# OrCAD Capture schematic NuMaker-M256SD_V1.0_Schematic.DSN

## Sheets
1 Nu-Link2-Me: size A3; title: Nu-Link2-Me; rev: 1.0; company: CMHuang; note: Nu-Link2-Me
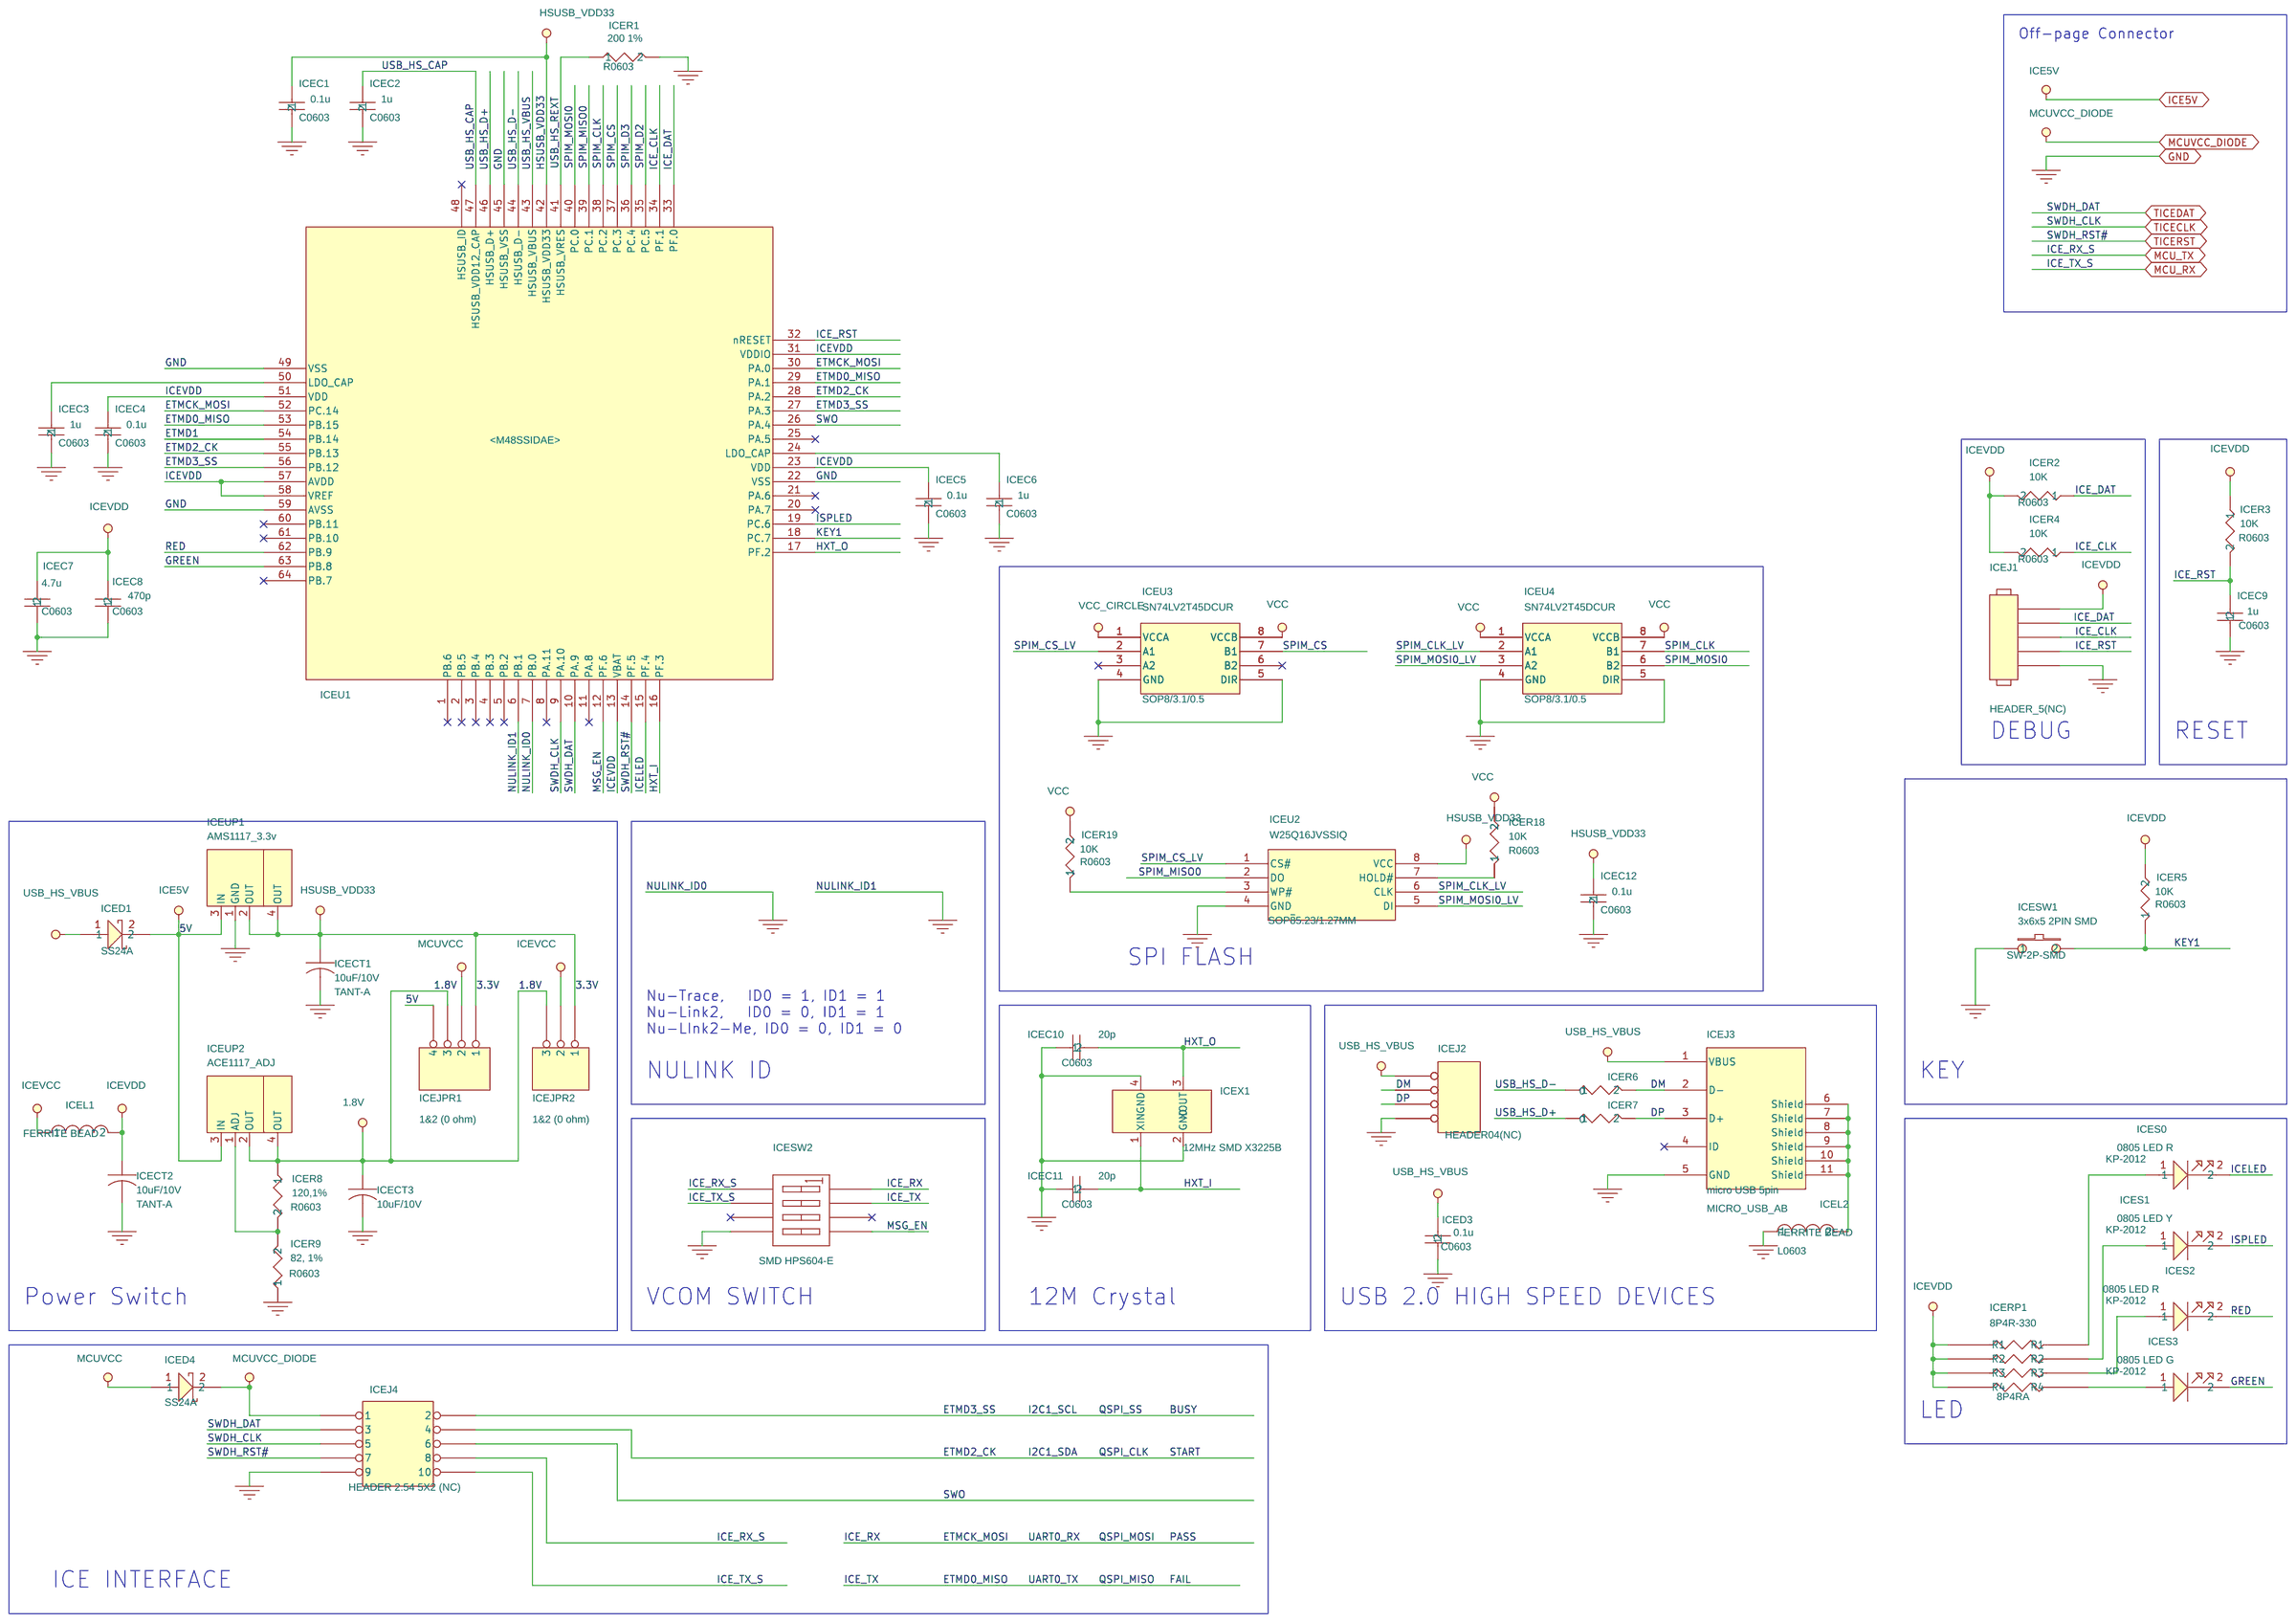
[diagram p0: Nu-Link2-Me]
2 M256SD2AE: size Custom; title: M256SD2AE; rev: v1.0; note: NuMaker-PFM-M256SD
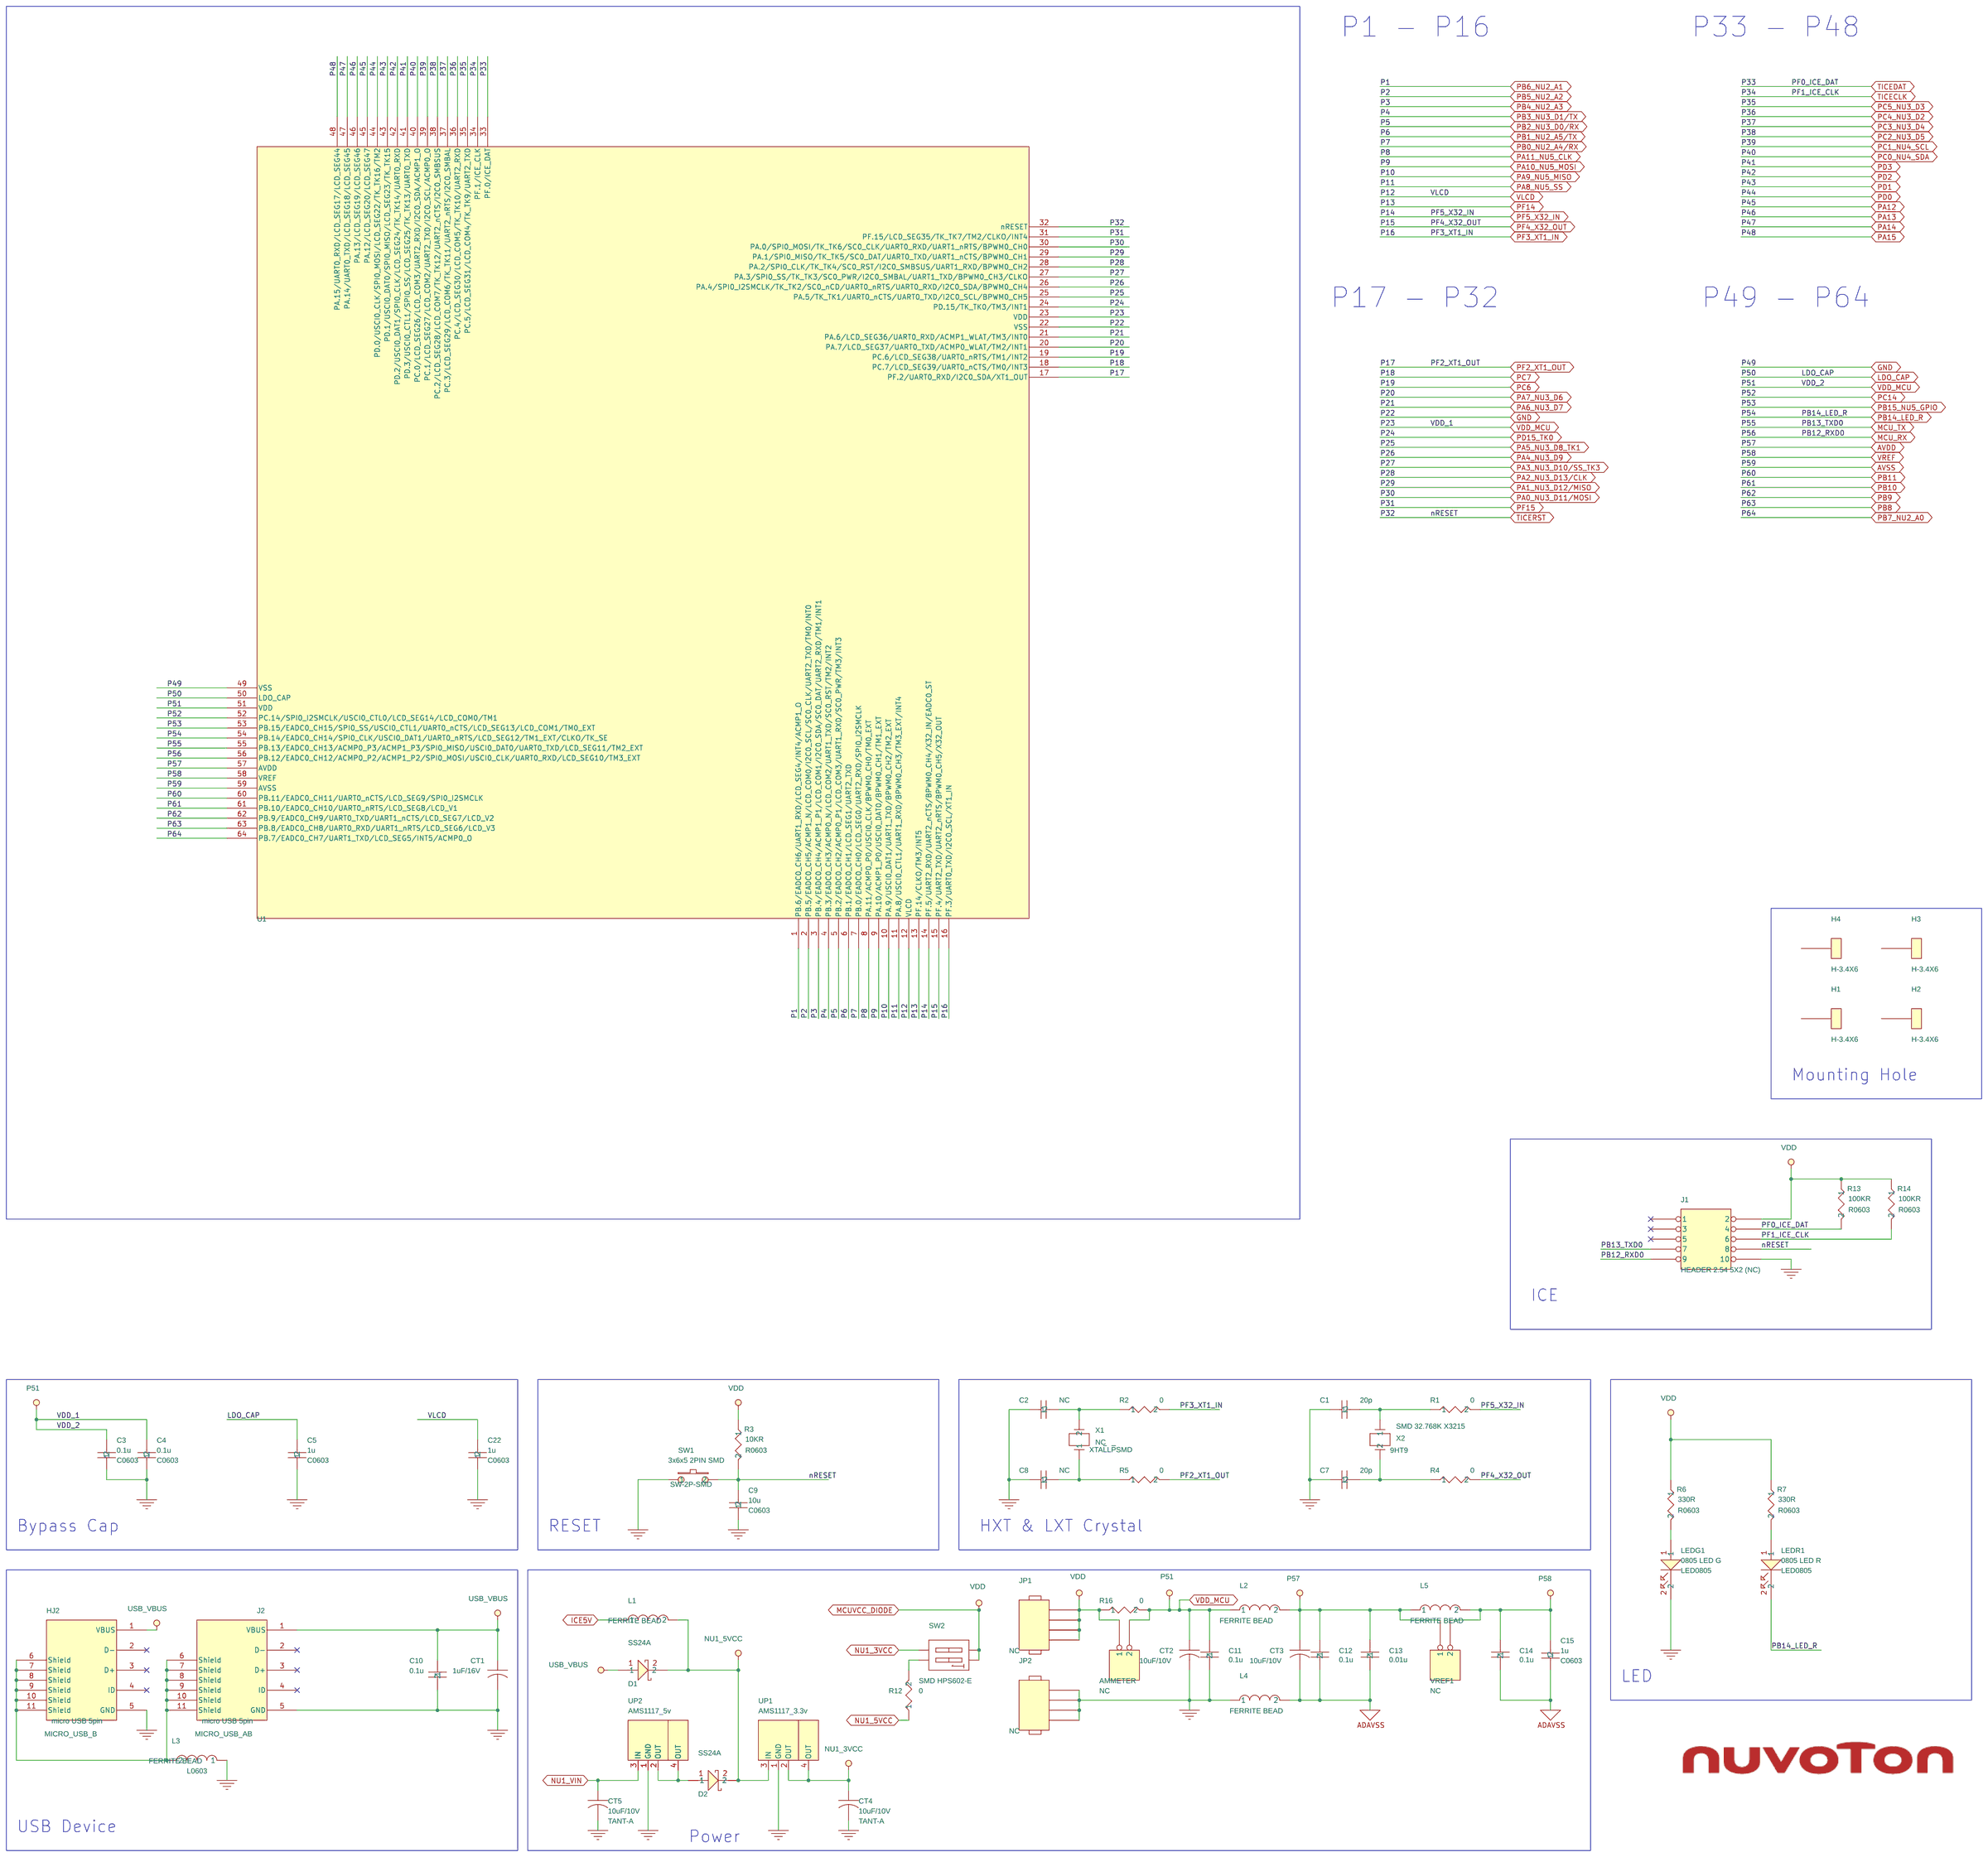
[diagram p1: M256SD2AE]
3 Ext. Connector: size Custom; title: Ext. Connector; rev: v1.0; note: NuMaker-PFM-M256SD
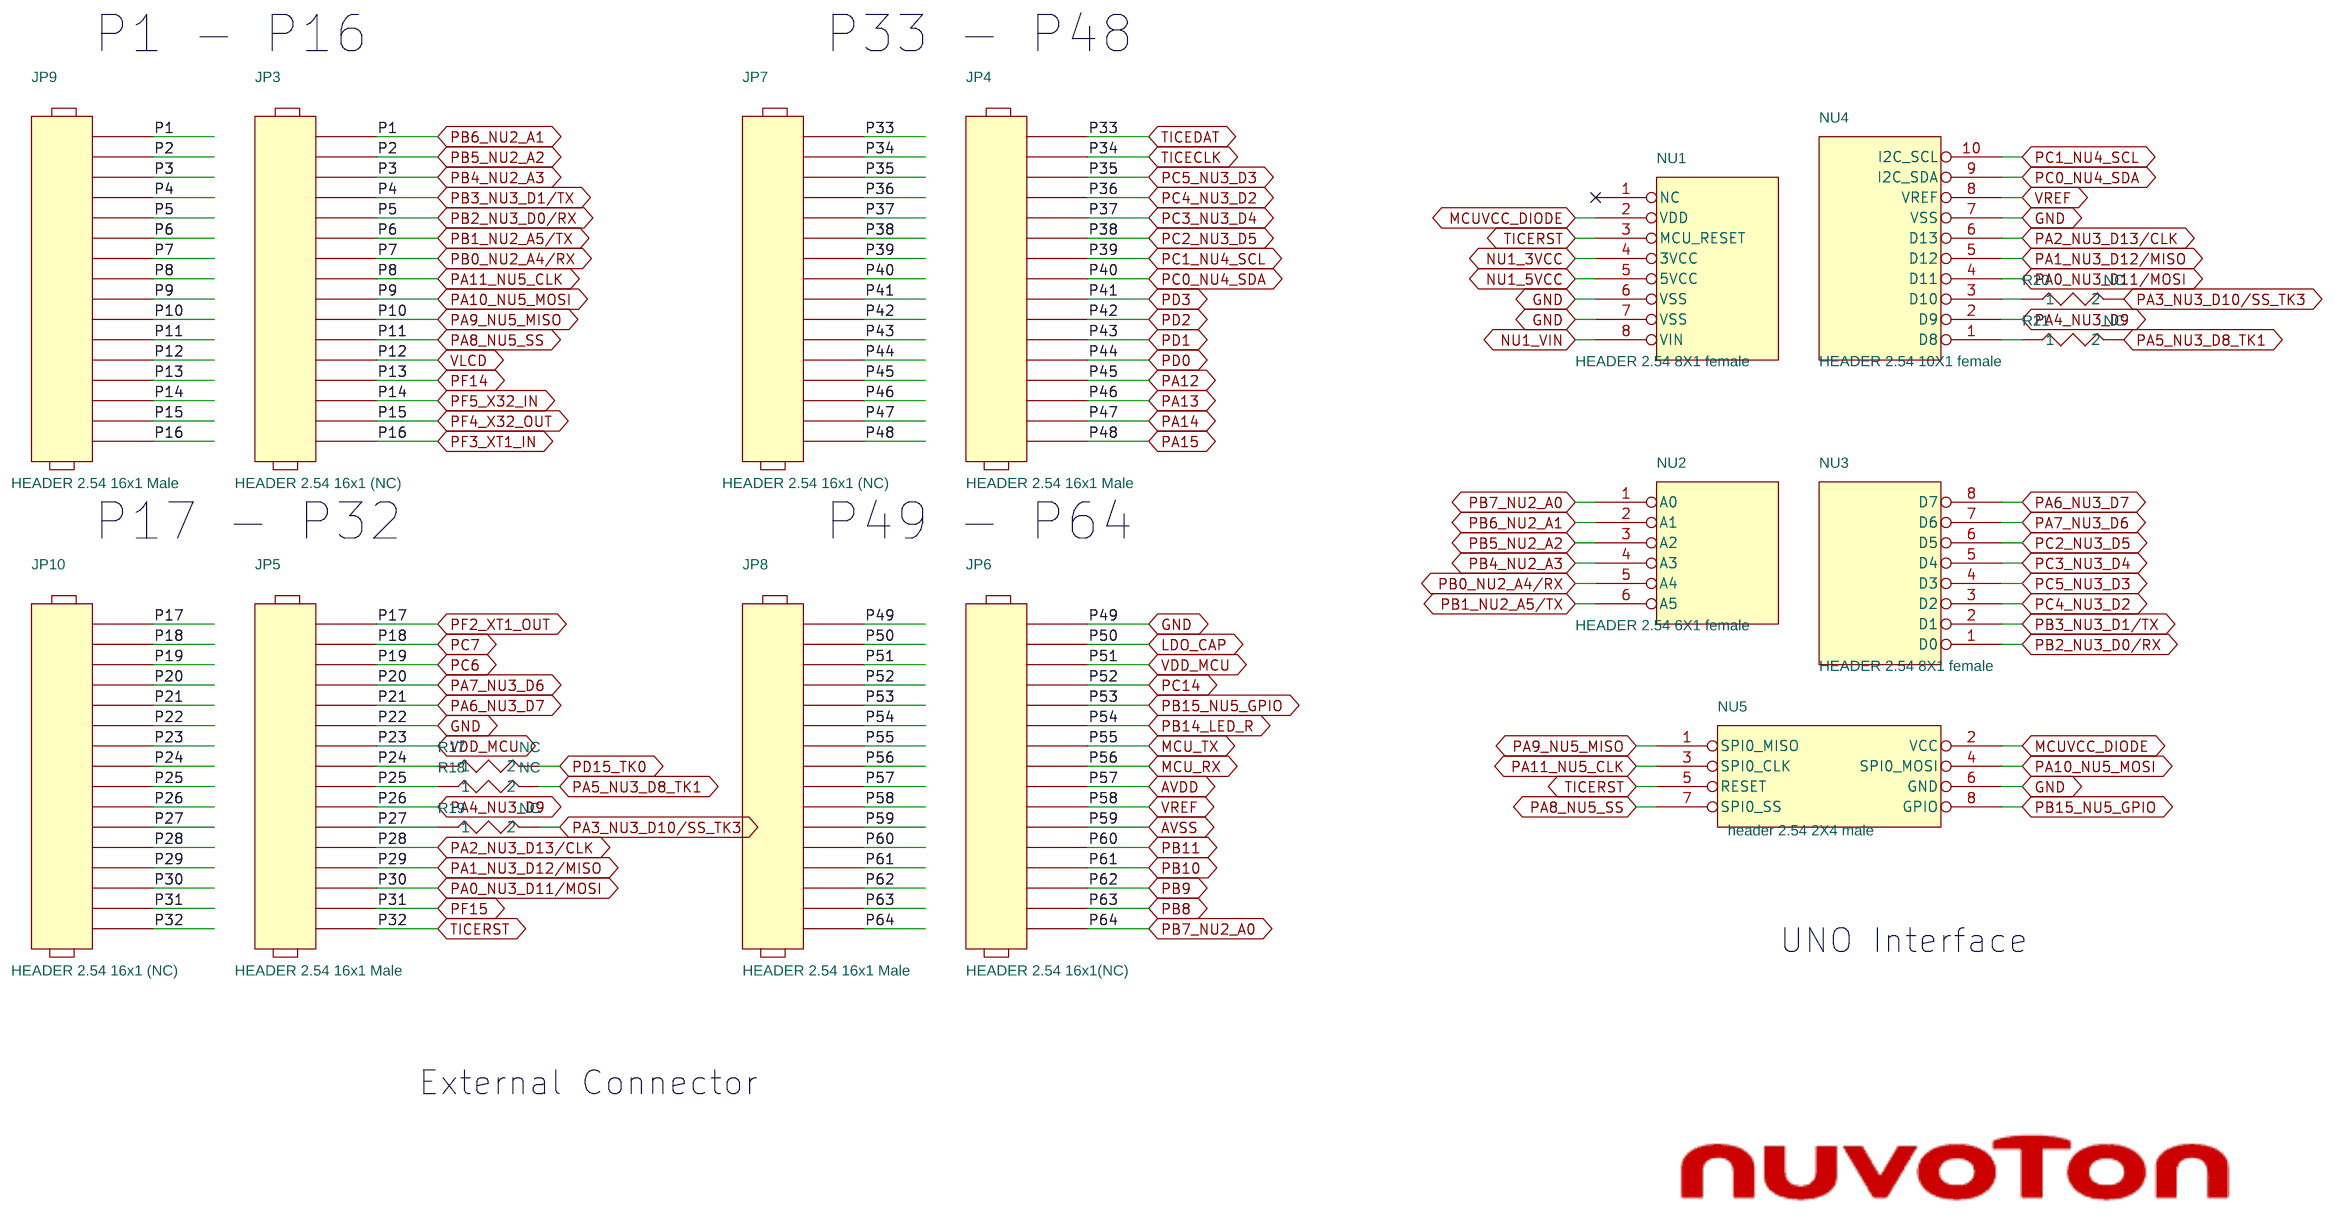
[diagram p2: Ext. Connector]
4 Touch Key: size A; title: Touch Key; rev: v1.0; note: NuMaker-PFM-M256SD
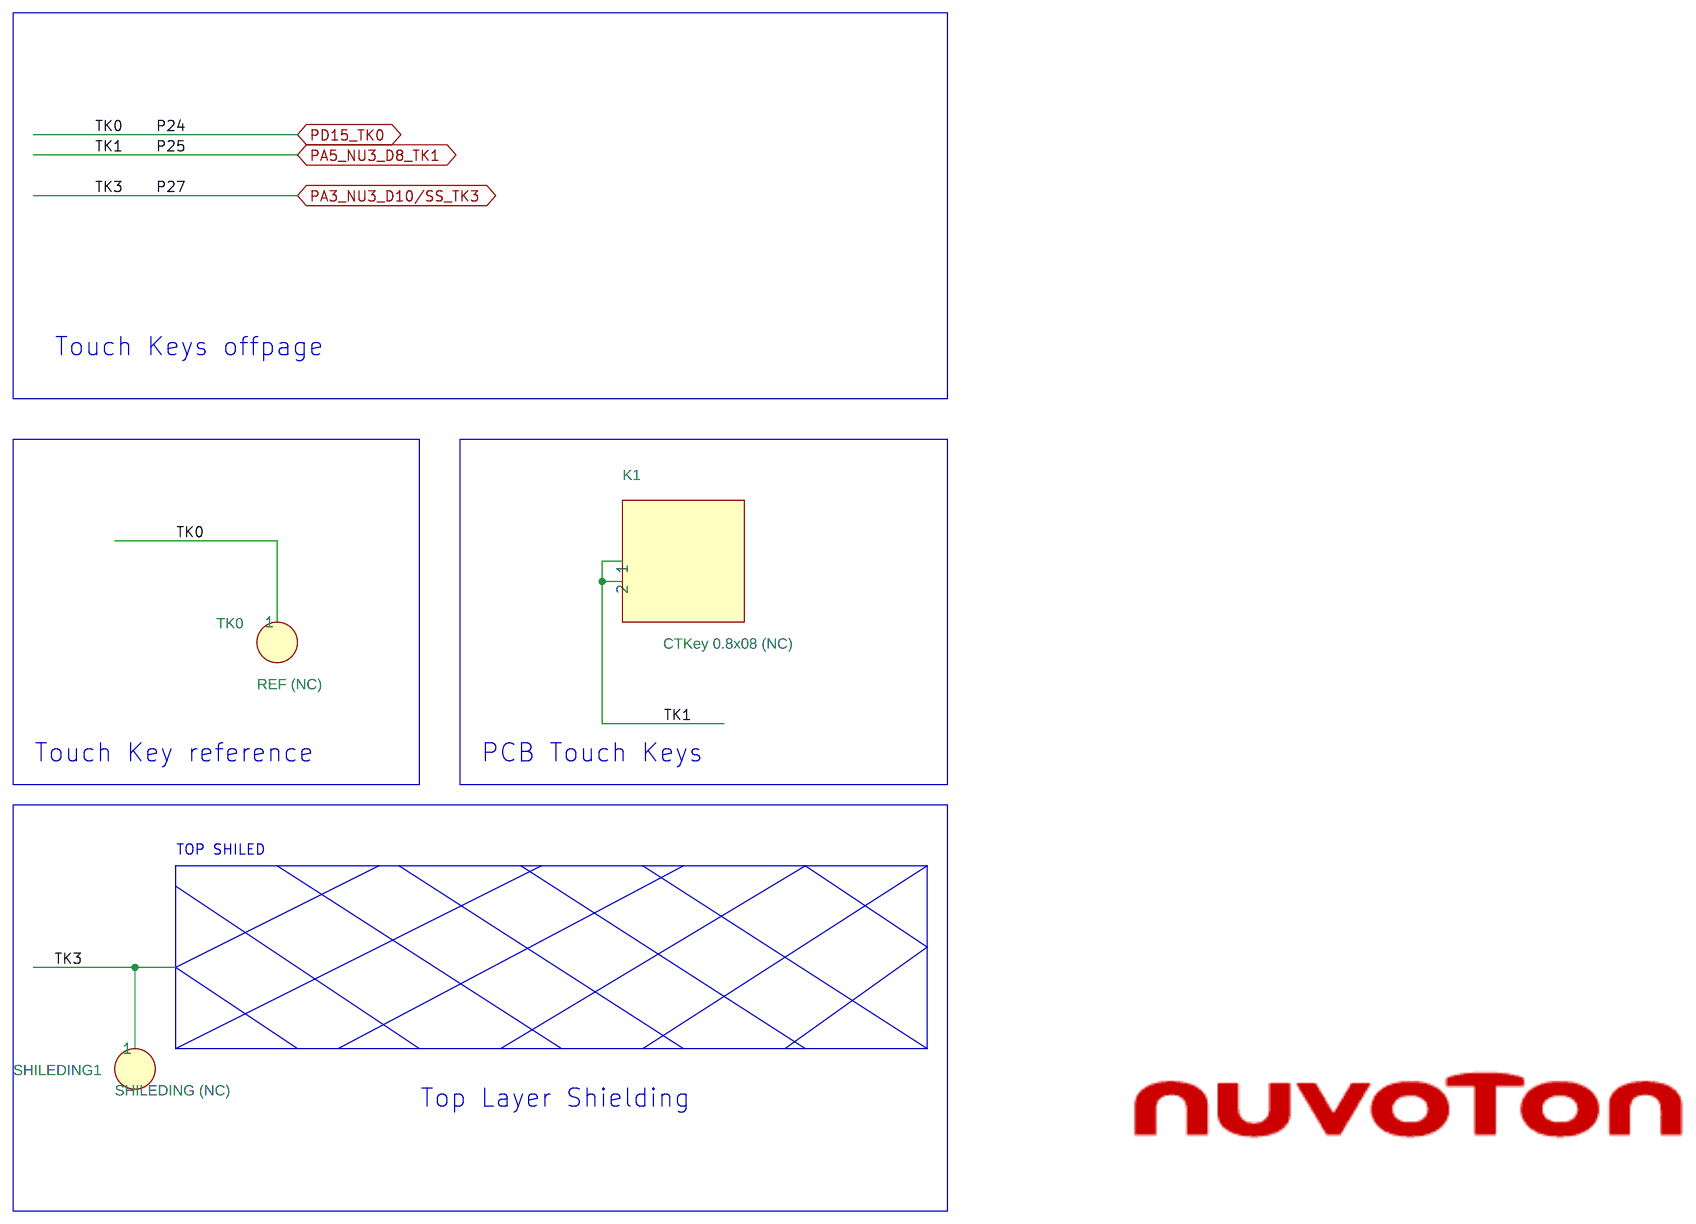
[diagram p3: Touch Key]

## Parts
sheet Ext. Connector
JP3  HEADER 2.54 16x1 (NC)  [HEADER16X1]
JP4  HEADER 2.54 16x1 Male  [HEADER16X1]
JP5  HEADER 2.54 16x1 Male  [HEADER16X1]
JP6  HEADER 2.54 16x1(NC)  [HEADER16X1]
JP7  HEADER 2.54 16x1 (NC)  [HEADER16X1]
JP8  HEADER 2.54 16x1 Male  [HEADER16X1]
JP9  HEADER 2.54 16x1 Male  [HEADER16X1]
JP10  HEADER 2.54 16x1 (NC)  [HEADER16X1]
NU1  HEADER 2.54 8X1 female  [SIP-8P]
NU2  HEADER 2.54 6X1 female  [SIP-6P]
NU3  HEADER 2.54 8X1 female  [SIP-8P]
NU4  HEADER 2.54 10X1 female  [SIP-10P]
NU5  header 2.54 2X4 male  [HEADER4X2]
R17  NC  [R0603]
R18  NC  [R0603]
R19  NC  [R0603]
R20  NC  [R0603]
R21  NC  [R0603]
sheet M256SD2AE
AMMETER  NC  [HEADER2X1]
C1  20p  [C0603]
C2  NC  [C0603]
C3  0.1u  [C0603]
C4  0.1u  [C0603]
C5  1u  [C0603]
C7  20p  [C0603]
C8  NC  [C0603]
C9  10u  [C0603]
C10  0.1u  [C0603]
C11  0.1u  [C0603]
C12  0.1u  [C0603]
C13  0.01u  [C0603]
C14  0.1u  [C0603]
C15  1u  [C0603]
C22  1u  [C0603]
CT1  1uF/16V  [TANT-A]
CT2  10uF/10V  [TANT-A]
CT3  10uF/10V  [TANT-A]
CT4  10uF/10V  [TANT-A]
CT5  10uF/10V  [TANT-A]
D1  SS24A  [RB060L]
D2  SS24A  [RB060L]
H1  H-3.4X6  [H-3.4X6]
H2  H-3.4X6  [H-3.4X6]
H3  H-3.4X6  [H-3.4X6]
H4  H-3.4X6  [H-3.4X6]
HJ2  micro USB 5pin  [MICRO_USB_B]
J1  HEADER 2.54 5X2 (NC)  [HEADER5X2]
J2  micro USB 5pin  [MICRO_USB_AB]
JP1  NC  [header1x4]
JP2  NC  [header1x4]
L1  FERRITE BEAD  [L0603]
L2  FERRITE BEAD  [L0603]
L3  FERRITE BEAD  [L0603]
L4  FERRITE BEAD  [L0603]
L5  FERRITE BEAD  [L0603]
LEDG1  0805 LED G  [LED0805]
LEDR1  0805 LED R  [LED0805]
R1  0  [R0603]
R2  0  [R0603]
R3  10KR  [R0603]
R4  0  [R0603]
R5  0  [R0603]
R6  330R  [R0603]
R7  330R  [R0603]
R12  0  [R0603]
R13  100KR  [R0603]
R14  100KR  [R0603]
R16  0  [R0603]
SW1  3x6x5 2PIN SMD  [SW-2P-SMD]
SW2  SMD HPS602-E  [SW1X2]
U1  M256SD2AE  [MCU_LQFP64_7X7mm]
UP1  AMS1117_3.3v  [SOT-223-1]
UP2  AMS1117_5v  [SOT-223-1]
VREF1  NC  [HEADER2X1]
X1  NC  [XTAL\LP\SMD]
X2  SMD 32.768K X3215  [9HT9]
sheet Nu-Link2-Me
ICEC1  0.1u  [C0603]
ICEC2  1u  [C0603]
ICEC3  1u  [C0603]
ICEC4  0.1u  [C0603]
ICEC5  0.1u  [C0603]
ICEC6  1u  [C0603]
ICEC7  4.7u  [C0603]
ICEC8  470p  [C0603]
ICEC9  1u  [C0603]
ICEC10  20p  [C0603]
ICEC11  20p  [C0603]
ICEC12  0.1u  [C0603]
ICECT1  10uF/10V  [TANT-A]
ICECT2  10uF/10V  [TANT-A]
ICECT3  10uF/10V  [TANT-A]
ICED1  SS24A  [RB060L]
ICED3  0.1u  [C0603]
ICED4  SS24A  [RB060L]
ICEJ1  HEADER_5(NC)  [HEADER5X1]
ICEJ2  HEADER04(NC)  [HEADER04]
ICEJ3  micro USB 5pin  [MICRO_USB_AB]
ICEJ4  HEADER 2.54 5X2 (NC)  [HEADER5X2]
ICEJPR1  1&2 (0 ohm)  [R0603X3]
ICEJPR2  1&2 (0 ohm)  [R0603X2]
ICEL1  FERRITE BEAD  [L0603]
ICEL2  FERRITE BEAD  [L0603]
ICER1  200 1%  [R0603]
ICER2  10K  [R0603]
ICER3  10K  [R0603]
ICER4  10K  [R0603]
ICER5  10K  [R0603]
ICER6  0  [R0603]
ICER7  0  [R0603]
ICER8  120,1%  [R0603]
ICER9  82, 1%  [R0603]
ICER18  10K  [R0603]
ICER19  10K  [R0603]
ICERP1  8P4R-330  [8P4RA]
ICES0  0805 LED R  [KP-2012]
ICES1  0805 LED Y  [KP-2012]
ICES2  0805 LED R  [KP-2012]
ICES3  0805 LED G  [KP-2012]
ICESW1  3x6x5 2PIN SMD  [SW-2P-SMD]
ICESW2  SMD HPS604-E  [SW1X4]
ICEU1  M48SSIDAE  [LQFP64_7x7_M48SSIDAE]
ICEU2  W25Q16JVSSIQ  [SOP8\5.23/1.27MM]
ICEU3  SN74LV2T45DCUR  [SOP8/3.1/0.5]
ICEU4  SN74LV2T45DCUR  [SOP8/3.1/0.5]
ICEUP1  AMS1117_3.3v  [SOT-223-1]
ICEUP2  ACE1117_ADJ  [SOT-223-1]
ICEX1  12MHz SMD X3225B  [CRYSTAL_SMD]
sheet Touch Key
K1  CTKey 0.8x08 (NC)  [PAD_8mm]
SHILEDING1  SHILEDING (NC)  [PAD1mm]
TK0  REF (NC)  [PAD1mm]

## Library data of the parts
JP3-JP10 = HEADER_16
NU1 = POWER_CONNECT_0
NU2 = ADC_CONNECT_1
NU3 = PWM0_CONNECT_0
NU4 = PWM1_CONNECT_1
NU5 = NuEdu_NU7
R16 R17 = R_0_2
R2 R18 = R_0_4
R19 = R_0
R1 R20 = R_0_1
R5 R21 = R_0_3
AMMETER = HEADER_2_1
C1 = C_20p_3
C2 = C_20p
C3 = CAP-C_4: Package: 0603; element_no: C0004
C4 ICEC5 = CAP-C: Package: 0603; element_no: C0004
C5 = CAP-C_2: Package: 0603; element_no: C0006
C7 = C_20p_1
C8 = C_20p_2
C9 = CAP-C_5: Package: 0603; element_no: C0006
C10 = C_0.1u_3: element_no: C0004
C11 = C_0.1u: element_no: C0004
C12 = C_0.1u_2: element_no: C0004
C13 = C_0.1u_4: element_no: C0003
C14 = C_0.1u_1: element_no: C0004
C15 ICEC3 = CAP-C_3: Package: 0603; element_no: C0006
C22 = CAP-C_1: Package: 0603; element_no: C0006
CT1 = C_1uF_16V
CT2-CT5 ICECT1-ICECT3 = C_10uF_10V
D1 ICED4 = D_SS24A
D2 ICED1 = D_SS24A_1
H1-H4 = TEST_POINT
HJ2 ICEJ3 J2 = micro_USB_5pin_0
ICEJ4 J1 = HEADER_5X2
JP1 JP2 = HEADER_4
L1 = FERRITE_BEAD_4
L2 = FERRITE_BEAD_2
L3 = FERRITE_BEAD_3
ICEL2 L4 = FERRITE_BEAD_1
ICEL1 L5 = FERRITE_BEAD
LEDG1 = LED_0_1: Package: KP-2012; Vendor: Kingbright
LEDR1 = LED_0: Package: KP-2012; Vendor: Kingbright
ICER1 R3 = R_0_5: Package: 0603
R4 = R_0_10
ICER5 R6 = R_0_8: Package: 0603
ICER8 R7 = R_0: Package: 0603
R12 = R_0_7
ICER18 R13 = R_0_6: Package: 0603
R14 = R_0_9: Package: 0603
ICESW1 SW1 = SW_PUSHBUTTON_0
SW2 = SW_DIP-4_2
U1 = M256SD2AE
ICEUP1 UP1 UP2 = TO-247_Regulator_10
VREF1 = HEADER_2
X1 = Xtal_12MHz
X2 = Xtal_32.768K
ICEC1 = CAP-C_11: Package: 0603; element_no: C0004
ICEC2 = CAP-C_9: Package: 0603; element_no: C0006
ICEC4 = CAP-C_10: Package: 0603; element_no: C0004
ICEC6 = CAP-C_12: Package: 0603; element_no: C0006
ICEC7 = CAP-C_5: Package: 0603
ICEC8 = CAP-C_6: Package: 0603
ICEC9 = CAP-C_7: Package: 0603; element_no: C0006
ICEC10 = CAP-C_2: Package: 0603
ICEC11 = CAP-C_4: Package: 0603
ICEC12 = CAP-C_8: Package: 0603; element_no: C0004
ICED3 = CAP-C_1: Package: 0603; element_no: C0004
ICEJ1 = HEADER_5_v2
ICEJ2 = HEADER_4_v2
ICEJPR1 = HEADER_3_0
ICEJPR2 = HEADER_3
ICER2 = R_0_1: Package: 0603
ICER3 = R_0_4: Package: 0603
ICER4 = R_0_3: Package: 0603
ICER6 = R_33
ICER7 = R_33_1
ICER9 = R_0_2: Package: 0603
ICER19 = R_0_7: Package: 0603
ICERP1 = R-PACK8_0
ICES0 = LED_0_3: Vendor: Kingbright
ICES1 = LED_0_2: Vendor: Kingbright
ICES2 = LED_0_1: Vendor: Kingbright
ICES3 = LED_0: Vendor: Kingbright
ICESW2 = SW_DIP-4_SM
ICEU1 = M487SIDAE_0: M487SIDAE: <M48SSIDAE>
ICEU2 = W25P10_20_40_SOIC_0: Package: SOP8; Vendor: WINBOND
ICEU3 ICEU4 = SN74LV2T45
ICEUP2 = TO-247_Regulator_0
ICEX1 = Crystal_SMD_1
K1 = CTKey_0
SHILEDING1 TK0 = CTKey_7

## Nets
1.8V: ICECT3.1 ICEJPR1.3 ICEJPR2.3 ICER8.1 ICEUP2.2(OUT) ICEUP2.4(OUT)
3.3V: ICEC1.1 ICEC12.1 ICECT1.1 ICEJPR1.1 ICEJPR2.1 ICER18.2 ICER19.2 ICEU1.42(HSUSB_VDD33) ICEU2.8(VCC) ICEU3.1(VCCA) ICEU4.1(VCCA) ICEUP1.2(OUT) ICEUP1.4(OUT)
AVDD: C12.1 C13.1 CT3.1 JP6.9 JP8.9 L2.2 L5.1 U1.57(AVDD) VREF1.1
AVSS: C12.2 C13.2 C14.2 C15.1 CT3.2 JP6.11 JP8.11 L4.2 U1.59(AVSS)
GND: C1.1 C2.1 C3.1 C4.1 C5.1 C7.1 C8.1 C9.1 C10.2 C11.2 C22.1 CT1.2 CT2.2 CT4.2 CT5.2 HJ2.5(GND) ICEC1.2 ICEC2.2 ICEC3.2 ICEC4.2 ICEC5.2 ICEC6.2 ICEC7.1 ICEC8.1 ICEC9.1 ICEC10.1 ICEC11.1 ICEC12.2 ICECT1.2 ICECT2.2 ICECT3.2 ICED3.1 ICEJ1.5 ICEJ2.4 ICEJ3.5(GND) ICEJ4.9 ICEL2.1 ICER1.2 ICER9.1 ICESW1.1 ICESW2.4(A4) ICEU1.6(PB.1) ICEU1.7(PB.0) ICEU1.22(VSS) ICEU1.45(HSUSB_VSS) ICEU1.49(VSS) ICEU1.59(AVSS) ICEU2.4(GND) ICEU3.4(GND) ICEU3.5(DIR) ICEU4.4(GND) ICEU4.5(DIR) ICEUP1.1(GND) ICEX1.2(GND) ICEX1.4(GND) J1.10 J2.5(GND) JP2.1 JP2.2 JP2.3 JP2.4 JP5.6 JP6.1 JP8.1 JP10.6 L3.1 L4.1 LEDG1.2 NU1.6(VSS) NU1.7(VSS) NU4.7(VSS) NU5.6(GND) SW1.1 U1.22(VSS) U1.49(VSS) UP1.1(GND) UP2.1(GND)
VDD: AMMETER.1 ICED4.2 ICEJ4.1 J1.2 JP1.1 JP1.2 JP1.3 JP1.4 NU1.2(VDD) NU5.2(VCC) R3.1 R6.1 R7.1 R13.1 R14.1 R16.1 SW2.3(B1) SW2.4(B2)
VDD_MCU: AMMETER.2 C3.2 C4.2 C11.1 CT2.1 JP5.7 JP6.3 JP8.3 JP10.7 L2.1 R16.2 U1.23(VDD) U1.51(VDD)
BUSY: ICEJ4.2 ICEU1.27(PA.3) ICEU1.56(PB.12)
DM: ICEJ2.2 ICEJ3.2(D-) ICER6.2
DP: ICEJ2.3 ICEJ3.3(D+) ICER7.2
ETMD1: ICEU1.54(PB.14)
ETMD2_CK: ICEJ4.4 ICEU1.28(PA.2) ICEU1.55(PB.13)
GREEN: ICES3.2 ICEU1.63(PB.8)
HXT_I: ICEC11.2 ICEU1.16(PF.3) ICEX1.1(XIN)
HXT_O: ICEC10.2 ICEU1.17(PF.2) ICEX1.3(XOUT)
ICE5V: ICED1.2 ICEJPR1.4 ICEUP1.3(IN) ICEUP2.3(IN) L1.1
ICE_CLK: ICEJ1.3 ICER4.1 ICEU1.34(PF.1)
ICE_DAT: ICEJ1.2 ICER2.1 ICEU1.33(PF.0)
ICE_RST: ICEC9.2 ICEJ1.4 ICER3.2 ICEU1.32(nRESET)
ICE_RX: ICESW2.8(B1) ICEU1.30(PA.0) ICEU1.52(PC.14)
ICE_TX: ICESW2.7(B2) ICEU1.29(PA.1) ICEU1.53(PB.15)
ICELED: ICES0.2 ICEU1.15(PF.4)
ICEVCC: ICEJPR2.2 ICEL1.1
ICEVDD: ICEC4.1 ICEC5.1 ICEC7.2 ICEC8.2 ICECT2.1 ICEJ1.1 ICEL1.2 ICER2.2 ICER3.1 ICER4.2 ICER5.2 ICERP1.1(R1) ICERP1.3(R2) ICERP1.5(R3) ICERP1.7(R4) ICEU1.13(VBAT) ICEU1.23(VDD) ICEU1.31(VDDIO) ICEU1.51(VDD) ICEU1.57(AVDD) ICEU1.58(VREF) ICEU3.8(VCCB) ICEU4.8(VCCB)
ISPLED: ICES1.2 ICEU1.19(PC.6)
KEY1: ICER5.1 ICESW1.2 ICEU1.18(PC.7)
LDO_CAP: C5.2 JP6.2 JP8.2 U1.50(LDO_CAP)
MCU_RX: ICEJ4.10 ICESW2.2(A2) J1.9 JP6.8 JP8.8 U1.56(PB.12/EADC0_CH12/ACMP0_P2/ACMP1_P2/SPI0_MOSI/USCI0_CLK/UART0_RXD/LCD_SEG10/TM3_EXT)
MCU_TX: ICEJ4.8 ICESW2.1(A1) J1.7 JP6.7 JP8.7 U1.55(PB.13/EADC0_CH13/ACMP0_P3/ACMP1_P3/SPI0_MISO/USCI0_DAT0/UART0_TXD/LCD_SEG11/TM2_EXT)
MCUVCC: ICED4.1 ICEJPR1.2
MSG_EN: ICESW2.5(B4) ICEU1.12(PF.6)
NU1_3VCC: CT4.1 NU1.4(3VCC) SW2.2(A2) UP1.2(OUT) UP1.4(OUT)
NU1_5VCC: D1.2 D2.2 L1.2 NU1.5(5VCC) R12.1 UP1.3(IN)
NU1_VIN: CT5.1 NU1.8(VIN) UP2.3(IN)
P24: JP5.8 JP10.8 R17.1
P25: JP5.9 JP10.9 R18.1
P27: JP5.11 JP10.11 R19.1
PA0_NU3_D11/MOSI: JP5.14 JP10.14 NU4.4(D11) U1.30(PA.0/SPI0_MOSI/TK_TK6/SC0_CLK/UART0_RXD/UART1_nRTS/BPWM0_CH0)
PA1_NU3_D12/MISO: JP5.13 JP10.13 NU4.5(D12) U1.29(PA.1/SPI0_MISO/TK_TK5/SC0_DAT/UART0_TXD/UART1_nCTS/BPWM0_CH1)
PA2_NU3_D13/CLK: JP5.12 JP10.12 NU4.6(D13) U1.28(PA.2/SPI0_CLK/TK_TK4/SC0_RST/I2C0_SMBSUS/UART1_RXD/BPWM0_CH2)
PA3_NU3_D10/SS_TK3: R19.2 R20.2 SHILEDING1.1 U1.27(PA.3/SPI0_SS/TK_TK3/SC0_PWR/I2C0_SMBAL/UART1_TXD/BPWM0_CH3/CLKO)
PA4_NU3_D9: JP5.10 JP10.10 NU4.2(D9) U1.26(PA.4/SPI0_I2SMCLK/TK_TK2/SC0_nCD/UART0_nRTS/UART0_RXD/I2C0_SDA/BPWM0_CH4)
PA5_NU3_D8_TK1: K1.1 K1.2 R18.2 R21.2 U1.25(PA.5/TK_TK1/UART0_nCTS/UART0_TXD/I2C0_SCL/BPWM0_CH5)
PA6_NU3_D7: JP5.5 JP10.5 NU3.8(D7) U1.21(PA.6/LCD_SEG36/UART0_RXD/ACMP1_WLAT/TM3/INT0)
PA7_NU3_D6: JP5.4 JP10.4 NU3.7(D6) U1.20(PA.7/LCD_SEG37/UART0_TXD/ACMP0_WLAT/TM2/INT1)
PA8_NU5_SS: JP3.11 JP9.11 NU5.7(SPI0_SS) U1.11(PA.8/USCI0_CTL1/UART1_RXD/BPWM0_CH3/TM3_EXT/INT4)
PA9_NU5_MISO: JP3.10 JP9.10 NU5.1(SPI0_MISO) U1.10(PA.9/USCI0_DAT1/UART1_TXD/BPWM0_CH2/TM2_EXT)
PA10_NU5_MOSI: JP3.9 JP9.9 NU5.4(SPI0_MOSI) U1.9(PA.10/ACMP1_P0/USCI0_DAT0/BPWM0_CH1/TM1_EXT)
PA11_NU5_CLK: JP3.8 JP9.8 NU5.3(SPI0_CLK) U1.8(PA.11/ACMP0_P0/USCI0_CLK/BPWM0_CH0/TM0_EXT)
PA12: JP4.13 JP7.13 U1.45(PA.12/LCD_SEG20/LCD_SEG47)
PA13: JP4.14 JP7.14 U1.46(PA.13/LCD_SEG19/LCD_SEG46)
PA14: JP4.15 JP7.15 U1.47(PA.14/UART0_TXD/LCD_SEG18/LCD_SEG45)
PA15: JP4.16 JP7.16 U1.48(PA.15/UART0_RXD/LCD_SEG17/LCD_SEG44)
PB0_NU2_A4/RX: JP3.7 JP9.7 NU2.5(A4) U1.7(PB.0/EADC0_CH0/LCD_SEG0/UART2_RXD/SPI0_I2SMCLK)
PB1_NU2_A5/TX: JP3.6 JP9.6 NU2.6(A5) U1.6(PB.1/EADC0_CH1/LCD_SEG1/UART2_TXD)
PB2_NU3_D0/RX: JP3.5 JP9.5 NU3.1(D0) U1.5(PB.2/EADC0_CH2/ACMP0_P1/LCD_COM3/UART1_RXD/SC0_PWR/TM3/INT3)
PB3_NU3_D1/TX: JP3.4 JP9.4 NU3.2(D1) U1.4(PB.3/EADC0_CH3/ACMP0_N/LCD_COM2/UART1_TXD/SC0_RST/TM2/INT2)
PB4_NU2_A3: JP3.3 JP9.3 NU2.4(A3) U1.3(PB.4/EADC0_CH4/ACMP1_P1/LCD_COM1/I2C0_SDA/SC0_DAT/UART2_RXD/TM1/INT1)
PB5_NU2_A2: JP3.2 JP9.2 NU2.3(A2) U1.2(PB.5/EADC0_CH5/ACMP1_N/LCD_COM0/I2C0_SCL/SC0_CLK/UART2_TXD/TM0/INT0)
PB6_NU2_A1: JP3.1 JP9.1 NU2.2(A1) U1.1(PB.6/EADC0_CH6/UART1_RXD/LCD_SEG4/INT4/ACMP1_O)
PB7_NU2_A0: JP6.16 JP8.16 NU2.1(A0) U1.64(PB.7/EADC0_CH7/UART1_TXD/LCD_SEG5/INT5/ACMP0_O)
PB8: JP6.15 JP8.15 U1.63(PB.8/EADC0_CH8/UART0_RXD/UART1_nRTS/LCD_SEG6/LCD_V3)
PB9: JP6.14 JP8.14 U1.62(PB.9/EADC0_CH9/UART0_TXD/UART1_nCTS/LCD_SEG7/LCD_V2)
PB10: JP6.13 JP8.13 U1.61(PB.10/EADC0_CH10/UART0_nRTS/LCD_SEG8/LCD_V1)
PB11: JP6.12 JP8.12 U1.60(PB.11/EADC0_CH11/UART0_nCTS/LCD_SEG9/SPI0_I2SMCLK)
PB14_LED_R: JP6.6 JP8.6 LEDR1.2 U1.54(PB.14/EADC0_CH14/SPI0_CLK/USCI0_DAT1/UART0_nRTS/LCD_SEG12/TM1_EXT/CLKO/TK_SE)
PB15_NU5_GPIO: JP6.5 JP8.5 NU5.8(GPIO) U1.53(PB.15/EADC0_CH15/SPI0_SS/USCI0_CTL1/UART0_nCTS/LCD_SEG13/LCD_COM1/TM0_EXT)
PC0_NU4_SDA: JP4.8 JP7.8 NU4.9(I2C_SDA) U1.40(PC.0/LCD_SEG26/LCD_COM3/UART2_RXD/I2C0_SDA/ACMP1_O)
PC1_NU4_SCL: JP4.7 JP7.7 NU4.10(I2C_SCL) U1.39(PC.1/LCD_SEG27/LCD_COM2/UART2_TXD/I2C0_SCL/ACMP0_O)
PC2_NU3_D5: JP4.6 JP7.6 NU3.6(D5) U1.38(PC.2/LCD_SEG28/LCD_COM7/TK_TK12/UART2_nCTS/I2C0_SMBSUS)
PC3_NU3_D4: JP4.5 JP7.5 NU3.5(D4) U1.37(PC.3/LCD_SEG29/LCD_COM6/TK_TK11/UART2_nRTS/I2C0_SMBAL)
PC4_NU3_D2: JP4.4 JP7.4 NU3.3(D2) U1.36(PC.4/LCD_SEG30/LCD_COM5/TK_TK10/UART2_RXD)
PC5_NU3_D3: JP4.3 JP7.3 NU3.4(D3) U1.35(PC.5/LCD_SEG31/LCD_COM4/TK_TK9/UART2_TXD)
PC6: JP5.3 JP10.3 U1.19(PC.6/LCD_SEG38/UART0_nRTS/TM1/INT2)
PC7: JP5.2 JP10.2 U1.18(PC.7/LCD_SEG39/UART0_nCTS/TM0/INT3)
PC14: JP6.4 JP8.4 U1.52(PC.14/SPI0_I2SMCLK/USCI0_CTL0/LCD_SEG14/LCD_COM0/TM1)
PD0: JP4.12 JP7.12 U1.44(PD.0/USCI0_CLK/SPI0_MOSI/LCD_SEG22/TK_TK16/TM2)
PD1: JP4.11 JP7.11 U1.43(PD.1/USCI0_DAT0/SPI0_MISO/LCD_SEG23/TK_TK15)
PD2: JP4.10 JP7.10 U1.42(PD.2/USCI0_DAT1/SPI0_CLK/LCD_SEG24/TK_TK14/UART0_RXD)
PD3: JP4.9 JP7.9 U1.41(PD.3/USCI0_CTL1/SPI0_SS/LCD_SEG25/TK_TK13/UART0_TXD)
PD15_TK0: R17.2 TK0.1 U1.24(PD.15/TK_TK0/TM3/INT1)
PF2_XT1_OUT: JP5.1 JP10.1 R5.2 U1.17(PF.2/UART0_RXD/I2C0_SDA/XT1_OUT)
PF3_XT1_IN: JP3.16 JP9.16 R2.2 U1.16(PF.3/UART0_TXD/I2C0_SCL/XT1_IN)
PF4_X32_OUT: JP3.15 JP9.15 R4.2 U1.15(PF.4/UART2_TXD/UART2_nRTS/BPWM0_CH5/X32_OUT)
PF5_X32_IN: JP3.14 JP9.14 R1.2 U1.14(PF.5/UART2_RXD/UART2_nCTS/BPWM0_CH4/X32_IN/EADC0_ST)
PF14: JP3.13 JP9.13 U1.13(PF.14/CLKO/TM3/INT5)
PF15: JP5.15 JP10.15 U1.31(PF.15/LCD_SEG35/TK_TK7/TM2/CLKO/INT4)
RED: ICES2.2 ICEU1.62(PB.9)
SPIM_CLK: ICEU1.38(PC.2) ICEU4.7(B1)
SPIM_CLK_LV: ICEU2.6(CLK) ICEU4.2(A1)
SPIM_CS: ICEU1.37(PC.3) ICEU3.7(B1)
SPIM_CS_LV: ICEU2.1(CS#) ICEU3.2(A1)
SPIM_D2: ICEU1.35(PC.5)
SPIM_D3: ICEU1.36(PC.4)
SPIM_MISO0: ICEU1.39(PC.1) ICEU2.2(DO)
SPIM_MOSI0: ICEU1.40(PC.0) ICEU4.6(B2)
SPIM_MOSI0_LV: ICEU2.5(DI) ICEU4.3(A2)
SWO: ICEJ4.6 ICEU1.26(PA.4)
TICECLK: ICEJ4.5 ICEU1.9(PA.10) J1.6 JP4.2 JP7.2 R14.2 U1.34(PF.1/ICE_CLK)
TICEDAT: ICEJ4.3 ICEU1.10(PA.9) J1.4 JP4.1 JP7.1 R13.2 U1.33(PF.0/ICE_DAT)
TICERST: C9.2 ICEJ4.7 ICEU1.14(PF.5) J1.8 JP5.16 JP10.16 NU1.3(MCU_RESET) NU5.5(RESET) R3.2 SW1.2 U1.32(nRESET)
USB_HS_CAP: ICEC2.1 ICEU1.47(HSUSB_VDD12_CAP)
USB_HS_D+: ICER7.1 ICEU1.46(HSUSB_D+)
USB_HS_D-: ICER6.1 ICEU1.44(HSUSB_D-)
USB_HS_REXT: ICER1.1 ICEU1.41(HSUSB_VRES)
USB_HS_VBUS: ICED1.1 ICED3.2 ICEJ2.1 ICEJ3.1(VBUS) ICEU1.43(HSUSB_VBUS)
USB_VBUS: C10.1 CT1.1 D1.1 HJ2.1(VBUS) J2.1(VBUS)
VLCD: C22.2 JP3.12 JP9.12 U1.12(VLCD)
VREF: C14.1 C15.2 JP6.10 JP8.10 L5.2 NU4.8(VREF) U1.58(VREF) VREF1.2
N16825237: LEDG1.1 R6.2
N16825240: LEDR1.1 R7.2
N16840819: ICEC6.1 ICEU1.24(LDO_CAP)
N16840960: ICEC3.1 ICEU1.50(LDO_CAP)
N17019924: ICER8.2 ICER9.2 ICEUP2.1(ADJ)
N17029977: ICERP1.8(R4) ICES3.1
N17029979: ICERP1.6(R3) ICES2.1
N17030004: ICERP1.4(R2) ICES1.1
N17030010: ICERP1.2(R1) ICES0.1
N17042369: ICEJ3.6(Shield) ICEJ3.7(Shield) ICEJ3.8(Shield) ICEJ3.9(Shield) ICEJ3.10(Shield) ICEJ3.11(Shield) ICEL2.2
N17110356: HJ2.6(Shield) HJ2.7(Shield) HJ2.8(Shield) HJ2.9(Shield) HJ2.10(Shield) HJ2.11(Shield) J2.6(Shield) J2.7(Shield) J2.8(Shield) J2.9(Shield) J2.10(Shield) J2.11(Shield) L3.2
N17125028: R12.2 SW2.1(A1)
N17155328: ICER18.1 ICEU2.7(HOLD#)
N17155343: ICER19.1 ICEU2.3(WP#)
N17159369: C8.2 R5.1 X1.1
N17159371: C2.2 R2.1 X1.2
N17159463: C1.2 R1.1 X2.1
N17159465: C7.2 R4.1 X2.2
N17167442: D2.1 UP2.2(OUT) UP2.4(OUT)
N17176049: NU4.3(D10) R20.1
N17176053: NU4.1(D8) R21.1

Not connected (* = marked no-connect by the designer): H1 1; H2 1; H3 1; H4 1; HJ2 2(D-)* 3(D+)* 4(ID)*; ICEJ3 4(ID)*; ICESW2 3(A3)* 6(B3)*; ICEU1 1(PB.6)* 2(PB.5)* 3(PB.4)* 4(PB.3)* 5(PB.2)* 8(PA.11)* 11(PA.8)* 20(PA.7)* 21(PA.6)* 25(PA.5)* 48(HSUSB_ID)* 60(PB.11)* 61(PB.10)* 64(PB.7)*; ICEU3 3(A2)* 6(B2)*; J1 1* 3* 5*; J2 2(D-)* 3(D+)* 4(ID)*; NU1 1(NC)*

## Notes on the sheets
sheet 1
- Off-page Connector
- DEBUG
- RESET
- SPI FLASH
- Nu-Trace,   ID0 = 1, ID1 = 1
  Nu-Link2,   ID0 = 0, ID1 = 1
  Nu-LInk2-Me, ID0 = 0, ID1 = 0
- NULINK ID
- KEY
- Power Switch
- VCOM SWITCH
- 12M Crystal
- USB 2.0 HIGH SPEED DEVICES
- LED
- ICE INTERFACE
sheet 2
- P1 - P16
- P33 - P48
- P17 - P32
- P49 - P64
- Mounting Hole
- ICE
- Bypass Cap
- RESET
- HXT & LXT Crystal
- LED
- USB Device
- Power
sheet 3
- P1 - P16
- P33 - P48
- P17 - P32
- P49 - P64
- UNO Interface
- External Connector
sheet 4
- Touch Keys offpage
- Touch Key reference
- PCB Touch Keys
- TOP SHILED
- Top Layer Shielding
